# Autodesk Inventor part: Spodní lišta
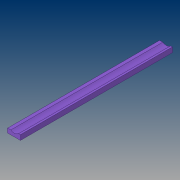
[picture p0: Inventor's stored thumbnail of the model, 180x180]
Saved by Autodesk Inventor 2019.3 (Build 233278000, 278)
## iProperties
Created: 2019-03
Part Number: Spodní lišta
Material: Hliník 6061-AHC
Document SubType Name: Modeling
Designer: B-hon
Density: 2.7 g/cm^3
Appearance: Fialová
Author: B-hon
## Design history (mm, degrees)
sketch "Náčrt1"
  geometry: L1 (0, 0)-(48, 0); L2 (48, 0)-(48, 18.5); L3 (48, 18.5)-(0, 18.5); L4 (0, 18.5)-(0, 0)
  constraints: 8 end point, 2 parallel, 1 horizontal, 1 perpendicular
  dimensions: "d0" = 48 distance of L3.end L2.end; "d1" = 18.5 distance of L2.end L1.end
extrude "Vysunutí1" new body sketch "Náčrt1" distance "d2" = 570; taper "d3" = 0 deg
sketch "Náčrt2"
  geometry: L1 (48, 0)-(48, 18.5) reference; L2 (0, 0)-(48, 0) reference; L3 (-7.001, 16)-(12.039, 16); L4 (-7.001, 16)-(-7.001, 35); L5 (-7.001, 35)-(2, 35); A1 r 23 centre (25, 35) between (12.039, 16) and (2, 35)
  constraints: 6 end point, 2 point on circle, 1 centre point, 1 horizontal, 1 perpendicular, 1 vertical
  dimensions: "d4" = 46 diameter of A1; "d5" = 23 distance from line of L1 A1.centre (= 0.5 x d4); "d6" = 12 distance edge to line of A1 L2; "d7" = 4 distance edge to line of A1 L3
extrude "Vysunutí2" cut sketch "Náčrt2" distance "d8" = 570; taper "d9" = 0 deg
node "Těleso1"
